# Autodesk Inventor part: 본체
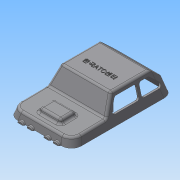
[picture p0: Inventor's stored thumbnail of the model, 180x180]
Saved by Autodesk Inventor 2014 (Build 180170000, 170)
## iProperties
Created: 2015-05
Part Number: 본체
Material: 일반
Document SubType Name: Modeling
Designer: Administrator
Density: 1 g/cm^3
Appearance: 기본값
Author: Administrator
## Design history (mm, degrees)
sketch "스케치5"
  geometry: L1 (0, 0)-(-122, 0); L2 (-122, 0)-(-119.249, 10.269); L3 (-119.249, 10.269)-(-77.932, 11); L4 (-77.932, 11)-(-67.133, 31); L5 (-67.133, 31)-(-21.792, 31); L6 (-21.792, 31)-(-3.909, 14.587); L7 (-3.909, 14.587)-(0, 0); L8 (0, 0)-(0, 11); L9 (-5.051, 15.636)-(0, 11)
  constraints: 18 end point, 2 horizontal, 1 collinear, 1 perpendicular, 1 point on line
  dimensions: "d44" = 122 distance of L1.start L1.end; "d45" = 105 deg angle of L2 L1; "d46" = 105 deg angle of L7 L1; "d47" = 31 distance between parallel lines of L1 L5; "d48" = 20 vertical distance of L3.end L4.end; "d49" = 20 vertical distance of L8.end L5.end
extrude "돌출5" new body sketch "스케치5" stored distance "d50" = 76; taper "d51" = 0 deg
node "작업 평면4"
sketch "스케치6"
  geometry: L1 (0, -114.412)-(0, -86.69); L2 (0, -86.69)-(-15.739, -92.736); L3 (-11, -77.932)-(-10.269, -119.249) reference; L4 (-15.739, -92.736)-(-15.449, -109.097); L5 (-15.449, -109.097)-(0, -114.412); L6 (-10.269, -119.249)-(0, -122) reference; L7 (-10.269, -119.249)-(-10.223, -121.828); L8 (0, -122)-(0, 0) reference; 2 further points
  constraints: 10 end point, 5 point on line, 1 parallel, 1 vertical
  dimensions: "d52" = 70 deg angle of L5 L3; "d53" = 70 deg angle of L2 L3; "d54" = 11 vertical distance of L7.end point (-10.418, -110.828); "d55" = 5 distance between parallel lines of L4 L3; "d56" = 20 vertical distance of point (-10.772, -90.828) point (-10.418, -110.828)
extrude "돌출6" join sketch "스케치6" stored distance "d57" = 26; taper "d58" = 0 deg
sketch "스케치9"
  geometry: L1 (38, 31)-(38, 0); L2 (-38, 0)-(-38, 31); L3 (-38, 0)-(-29.694, 31); L4 (29.694, 31)-(38, 0); L5 (-38, 31)-(-29.694, 31); L6 (29.694, 31)-(38, 31); L7 (38, 0)-(-38, 0) reference; L8 (38, 31)-(38, 14.587) reference; 5 further points
  constraints: 12 end point, 4 midpoint, 2 horizontal, 2 horizontal alignment, 2 perpendicular, 2 point on line, 1 parallel
  dimensions: "d74" = 15 deg angle of L1 L4; "d75" = 15 deg angle of L2 L3
extrude "돌출7" cut sketch "스케치9" stored distance "d76" = 26; taper "d77" = 0 deg
sketch "스케치10"
  geometry: L1 (-26, -64.151)-(-11, -72.249); L2 (-11, -72.249)-(-11, -38.249); L3 (-11, -38.249)-(-26, -38.249); L4 (-26, -38.249)-(-26, -64.151); L5 (-26, -35.395)-(-11, -35.395); L6 (-11, -35.395)-(-11, -7.395); L7 (-11, -7.395)-(-26, -23.739); L8 (-26, -23.739)-(-26, -35.395); L9 (-11, -77.932)-(-31, -67.133) reference; L10 (-31, -67.133)-(-31, -21.792) reference; L11 (-31, -21.792)-(-14.587, -3.909) reference; 1 further point
  constraints: 16 end point, 4 perpendicular, 3 parallel, 1 vertical
  dimensions: "d79" = 34 distance of L1.end L2.end; "d80" = 5 distance between parallel lines of L9 L1; "d81" = 5 distance between parallel lines of L11 L7; "d82" = 5 distance between parallel lines of L10 L8; "d83" = 5 distance between parallel lines of L10 L4; "d84" = 15 distance between parallel lines of L4 L2; "d86" = 28 distance of L5.end L6.end; "d130" = 15 horizontal distance of L6.end L7.end
fillet "모깎기2" dims "d87" = 12
feature "쉘3" dims "d88" = 2
extrude "돌출8" cut sketch "스케치10" stored distance "d89" = 26; taper "d90" = 0 deg
fillet "모깎기3" dims "d91" = 3
fillet "모깎기4" dims "d92" = 3
fillet "모깎기5" dims "d93" = 3
fillet "모깎기6" dims "d94" = 3
fillet "모깎기7" dims "d95" = 3
sketch "스케치11"
  geometry: L1 (0.139, -2.071)-(52.679, -2.071) reference; L2 (62.338, -11.73)-(62.338, -110.27) reference; L3 (52.679, -119.929)-(0.139, -119.929) reference; L4 (-9.521, -110.27)-(-9.521, -11.73) reference; L5 (52.818, 0)-(0, 0) reference; L6 (-11.591, -110.409)-(-11.591, -11.591) reference; L7 (0, -122)-(52.818, -122) reference; L8 (64.409, -11.591)-(64.409, -110.409) reference; 9 further points; 8 other entities
  constraints: 8 other
sketch "스케치12"
  geometry: L1 (0, 0)-(54.783, 0) reference; L2 (0.983, 22.96)-(53.8, 22.96) reference; 3 further points
  constraints: 1 midpoint, 1 vertical alignment, 1 other
  dimensions: "d96" = 50 distance of point (27.392, 22.96) point (27.392, -27.04)
feature "엠보싱1" sketch "스케치12" dims "d55" = 5, "d97" = 0.5, "d98" = 0
node "작업 평면5"
sketch "스케치13"
  geometry: L1 (-32.409, 0)-(-20.409, 0); L2 (-51.409, 0)-(-43.409, 0); L3 (-40.409, 0)-(-32.409, 0); L4 (-20.409, 0)-(-12.409, 0); L5 (-9.409, 0)-(-1.409, 0); A1 r 4 centre (-47.409, 0) between (-43.409, 0) and (-51.409, 0); A2 r 4 centre (-36.409, 0) between (-32.409, 0) and (-40.409, 0); A3 r 4 centre (-16.409, 0) between (-12.409, 0) and (-20.409, 0); A4 r 4 centre (-5.409, 0) between (-1.409, 0) and (-9.409, 0); 3 further points
  constraints: 10 end point, 10 point on circle, 4 centre point, 1 coincident, 1 collinear, 1 midpoint
  dimensions: "d100" = 4 radius of A1; "d101" = 4 radius of A2; "d102" = 4 radius of A3; "d103" = 4 radius of A4; "d104" = 11 distance of A2.centre A1.centre; "d105" = 11 distance of A4.centre A3.centre; "d106" = 20 distance of A2.centre A3.centre; "d107" = 8 distance of L5.start L5.end; "d108" = 8 distance of L1.end L4.end
extrude "돌출9" join sketch "스케치13" stored distance "d109" = 4; taper "d110" = 0 deg
chamfer "모따기1" distance "d111" = 1; stored, may be unused: second distance "d112" = 2, angle "d113" = 45 deg
extrude "돌출10" cut sketch "스케치11" distance "d122" = 1; taper "d123" = 0 deg
sketch "스케치16"
  geometry: L1 (7, 2)-(-1, 2) reference; L2 (-1, 1)-(-1, 2) reference; L3 (0, 0)-(-1, 1) reference; L4 (6, 0)-(0, 0) reference; L5 (7, 1)-(6, 0) reference; L6 (7, 2)-(7, 1) reference; L7 (7, 2)-(-1, 2) reference; L8 (-1, 1)-(-1, 2) reference; L9 (0, 0)-(-1, 1) reference; L10 (6, 0)-(0, 0) reference; L11 (7, 1)-(6, 0) reference; L12 (7, 2)-(7, 1) reference; L13 (18, 2)-(10, 2) reference; L14 (10, 1)-(10, 2) reference; L15 (11, 0)-(10, 1) reference; L16 (17, 0)-(11, 0) reference; L17 (18, 1)-(17, 0) reference; L18 (18, 2)-(18, 1) reference; L19 (38, 2)-(30, 2) reference; L20 (30, 1)-(30, 2) reference; L21 (31, 0)-(30, 1) reference; L22 (37, 0)-(31, 0) reference; L23 (38, 1)-(37, 0) reference; L24 (38, 2)-(38, 1) reference; L25 (49, 2)-(41, 2) reference; L26 (41, 1)-(41, 2) reference; L27 (42, 0)-(41, 1) reference; L28 (48, 0)-(42, 0) reference; L29 (49, 1)-(48, 0) reference; L30 (49, 2)-(49, 1) reference; 1 further point
extrude "돌출11" cut sketch "스케치16" distance "d124" = 1; taper "d125" = 0 deg
sketch "스케치21"
  geometry: C1 r 2 at (26.409, -100.945); C2 r 2 at (26.409, -22.585); C3 r 2 at (5.409, -61); C4 r 2 at (44.58, -61); 1 further point
  constraints: 4 centre point
  dimensions: "d138" = 4 diameter of C1; "d139" = 4 diameter of C2; "d140" = 4 diameter of C3; "d141" = 4 diameter of C4
extrude "돌출13" join sketch "스케치21" stored distance "d142" = 61.5; taper "d143" = 0 deg
sketch "스케치22"
  geometry: L1 (-0.5, -5)-(0.5, -5); L2 (0.5, -5)-(0.5, 5); L3 (0.5, 5)-(-0.5, 5); L4 (-0.5, 5)-(-0.5, -5); L5 (-0.5, -5)-(0.5, 5); L6 (0.5, -5)-(-0.5, 5); L7 (-20.5, 34.945)-(-20.5, 44.945); L8 (-21.5, 44.945)-(-21.5, 34.945); L9 (-20.5, 44.945)-(-21.5, 44.945); L10 (-21.5, 34.945)-(-20.5, 34.945); L11 (0.5, 73.36)-(0.5, 83.36); L12 (-0.5, 83.36)-(-0.5, 73.36); L13 (0.5, 83.36)-(-0.5, 83.36); L14 (-0.5, 73.36)-(0.5, 73.36); L15 (18.672, 34.945)-(18.672, 44.945); L16 (17.672, 44.945)-(17.672, 34.945); L17 (18.672, 44.945)-(17.672, 44.945); L18 (17.672, 34.945)-(18.672, 34.945); C1 r 2 at (0, 0) reference; C2 r 2 at (18.172, 39.945) reference; C3 r 2 at (-21, 39.945) reference; C4 r 2 at (0, 78.36) reference; 1 further point
  constraints: 36 end point, 8 parallel, 4 horizontal, 4 perpendicular, 2 midpoint
  dimensions: "d144" = 10 distance of L3.end L1.start; "d145" = 1 distance of L2.end L3.end; "d146" = 10 distance of L8.start L8.end; "d147" = 1 distance of L7.end L8.start; "d148" = 10 distance of L12.start L12.end; "d149" = 1 distance of L11.end L12.start; "d150" = 10 distance of L16.start L16.end; "d151" = 1 distance of L15.end L16.start
extrude "돌출14" join sketch "스케치22" stored distance "d152" = 0; taper "d153" = 0 deg
sketch "스케치23"
  geometry: L1 (26.909, -99.009)-(26.909, -95.945) reference; L2 (26.909, -95.945)-(25.909, -95.945) reference; L3 (25.909, -95.945)-(25.909, -99.009) reference; L4 (25.909, -102.882)-(25.909, -105.945) reference; L5 (25.909, -105.945)-(26.909, -105.945) reference; L6 (26.909, -105.945)-(26.909, -102.882) reference; L7 (45.08, -56)-(45.08, -59.064) reference; L8 (44.08, -56)-(45.08, -56) reference; L9 (44.08, -59.064)-(44.08, -56) reference; L10 (44.08, -66)-(44.08, -62.936) reference; L11 (45.08, -66)-(44.08, -66) reference; L12 (45.08, -62.936)-(45.08, -66) reference; L13 (5.909, -56)-(5.909, -59.064) reference; L14 (4.909, -56)-(5.909, -56) reference; L15 (4.909, -59.064)-(4.909, -56) reference; L16 (4.909, -66)-(4.909, -62.936) reference; L17 (5.909, -66)-(4.909, -66) reference; L18 (5.909, -62.936)-(5.909, -66) reference; A1 r 2 centre (26.409, -22.585) between (25.909, -20.649) and (25.909, -24.522) reference; A2 r 2 centre (26.409, -100.945) between (26.909, -102.882) and (26.909, -99.009) reference; A3 r 2 centre (26.409, -100.945) between (25.909, -99.009) and (25.909, -102.882) reference; A4 r 2 centre (44.58, -61) between (45.08, -62.936) and (45.08, -59.064) reference; A5 r 2 centre (44.58, -61) between (44.08, -59.064) and (44.08, -62.936) reference; A6 r 2 centre (5.409, -61) between (5.909, -62.936) and (5.909, -59.064) reference; A7 r 2 centre (5.409, -61) between (4.909, -59.064) and (4.909, -62.936) reference; 5 further points
  constraints: 4 coincident
hole "구멍1" sketch "스케치23" at (5.409, -61), (26.409, -100.945), (44.58, -61), (26.409, -22.585) diameter "d154" = 3.242; stored, may be unused: countersink angle "d158" = 90 deg, drill point angle "d160" = 118 deg; dims "d155" = 9, "d156" = 4, "d157" = 2, "d159" = 11
sketch "스케치24"
  geometry: C1 r 2 at (5.409, -61); C2 r 3 at (5.409, -61); C3 r 3 at (44.552, -61); C4 r 2 at (44.552, -61); C5 r 3 at (26.409, -22.596); C6 r 2 at (26.409, -22.596); C7 r 3 at (26.409, -100.941); C8 r 2 at (26.409, -100.941); A1 r 2 centre (5.409, -61) between (5.909, -62.936) and (5.909, -59.064) reference; A2 r 2 centre (5.409, -61) between (4.909, -59.064) and (4.909, -62.936) reference; 1 further point
  constraints: 8 centre point, 5 coincident, 1 concentric
  dimensions: "d161" = 6 diameter of C2; "d162" = 6 diameter of C3; "d163" = 6 diameter of C5; "d164" = 6 diameter of C7
extrude "돌출15" join sketch "스케치24" stored distance "d165" = 1; taper "d166" = 0 deg
node "솔리드2"
node "투영된 루프3"
node "투영된 루프4"
node "투영된 루프5"
node "투영된 루프6"
node "투영된 루프8"
node "투영된 루프9"
node "투영된 루프10"
other parameters: "d18" = 5, "d61" = 5
